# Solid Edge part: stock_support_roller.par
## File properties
Title: Stock support roller
Author: Deepak Maini
Template: Normal.par
Last saved by: CADCIM
Revision: 10
Application: Solid Edge
Accuracy: 0.99
Material: aluminum
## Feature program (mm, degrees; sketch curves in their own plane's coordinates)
sketch for "unnamed RevolvedProtrusion 1" plane through (0, 0, 0) normal (0, -1, 0) x-axis (1, 0, 0)
  line (60, 0) -> (60, 18.669)
  line (60, 18.669) -> (15.55, 18.669)
  line (15.55, 18.669) -> (15.55, 92.075)
  line (15.55, 92.075) -> (-2.2388, 92.075)
  line (-2.2388, 92.075) -> (-111.45, 29.0219)
  line (-220.6612, 92.075) -> (-111.45, 29.0219)
  line (-238.45, 92.075) -> (-220.6612, 92.075)
  line (-238.45, 18.669) -> (-238.45, 92.075)
  line (-282.9, 18.669) -> (-238.45, 18.669)
  line (-282.9, 0) -> (-282.9, 18.669)
revolve "unnamed RevolvedProtrusion 1" add full turn 360 deg about sketch line (-282.9, 0) -> (60, 0)
chamfer "unnamed Chamfer 1"
fillet "Round_1" radius 1.5748
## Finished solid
Body 1: solid body, 14 faces, 13 edges, 0 vertices.
  Faces by surface: cone 4, cylinder 4, plane 4, torus 2
  Edges by curve: circle 13
Bounding box of the edges (mm; curved faces can reach further): 342.900 x 184.150 x 184.150, from (-282.9, -92.075, -92.075) to (60, 92.075, 92.075).
Cylindrical faces by radius (mm): R18.669 x2, R92.075 x2
Conical faces (half-angle, radius in mm at the cone's reference point): 30 deg R29.0219 x1, 30 deg R92.075 x1, 45 deg R17.0942 x1, 45 deg R18.669 x1
Toroidal faces (ring radius, tube radius in mm): R20.2438 r1.5748 x2
Planar faces by outward normal: +x 2, -x 2
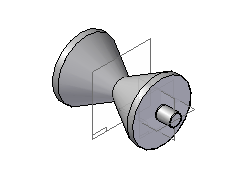
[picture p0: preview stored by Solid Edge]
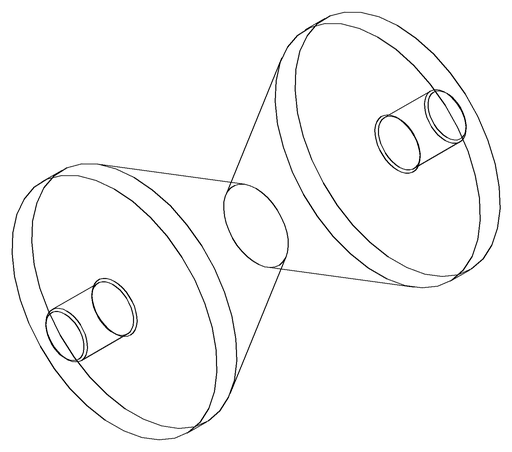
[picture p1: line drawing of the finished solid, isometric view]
